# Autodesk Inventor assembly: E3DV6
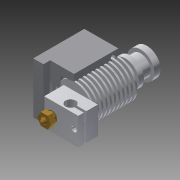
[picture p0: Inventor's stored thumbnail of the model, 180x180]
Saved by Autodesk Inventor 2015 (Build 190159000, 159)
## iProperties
Created: 2014-08
Part Number: E3DV6
Document SubType Name: Assembly
Designer: Jack
Author: Jack
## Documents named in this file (6)
- C:\Users\Jack\ownCloud\Projects\CoreXY\InventorModel\Extruder\E3DV6\E3DV6.iam
- C:\Users\Jack\ownCloud\Projects\CoreXY\InventorModel\Extruder\E3DV6\E3DV6HeatBreak.ipt
- C:\Users\Jack\ownCloud\Projects\CoreXY\InventorModel\Extruder\E3DV6\E3DV6HeatSink.ipt
- C:\Users\Jack\ownCloud\Projects\CoreXY\InventorModel\Extruder\E3DV6\E3DV6Nozzle.ipt
- C:\Users\Jack\ownCloud\Projects\CoreXY\InventorModel\Extruder\E3DV6\E3DV6NozzleBlock.ipt
- C:\Users\Jack\ownCloud\Projects\CoreXY\InventorModel\Extruder\E3DV6\E3DV6FanMount\E3DV6BodyFanMount.ipt
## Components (5 placed, 5 different names)
1. E3DV6HeatBreak:1 — Mate:1, Mate:2, Mate:3, Mate:5
2. E3DV6HeatSink:1 — Mate:1, Mate:2, Flush:2, Mate:6
3. E3DV6Nozzle:1 — Mate:4, Mate:5, Flush:1
4. E3DV6NozzleBlock:1 — Mate:3, Mate:4, Flush:1
5. E3DV6BodyFanMount:1 — Flush:2, Mate:6
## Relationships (8: Mate 6, Flush 2)
- Mate:1: E3DV6HeatBreak:1 ↔ E3DV6HeatSink:1
- Mate:2: E3DV6HeatBreak:1 ↔ E3DV6HeatSink:1
- Mate:3: E3DV6HeatBreak:1 ↔ E3DV6NozzleBlock:1
- Mate:4: E3DV6Nozzle:1 ↔ E3DV6NozzleBlock:1
- Mate:5: E3DV6HeatBreak:1 ↔ E3DV6Nozzle:1
- Flush:1: E3DV6Nozzle:1 ↔ E3DV6NozzleBlock:1
- Flush:2: E3DV6HeatSink:1 ↔ E3DV6BodyFanMount:1
- Mate:6: E3DV6HeatSink:1 ↔ E3DV6BodyFanMount:1
